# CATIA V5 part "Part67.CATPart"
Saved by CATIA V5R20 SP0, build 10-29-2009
Part number: FA 053000-2
Revision: ANY
Definition: UNKNOWN
Nomenclature: FA 053000-2
Source: Unknown
Bounding box of the stored display mesh (mm): x -1.5 to 1.5, y 0 to 3.7, z -1.5 to 1.5
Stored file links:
  C:\Users\Utente\Desktop\IO LAVORO\3D X SITO CF\CUMSA\3D files FA\FA 053000\Part67.CATPart

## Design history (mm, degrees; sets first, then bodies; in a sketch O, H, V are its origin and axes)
Body1 "Cortar-Extruir1" (main body)
  Solid1: solid without history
